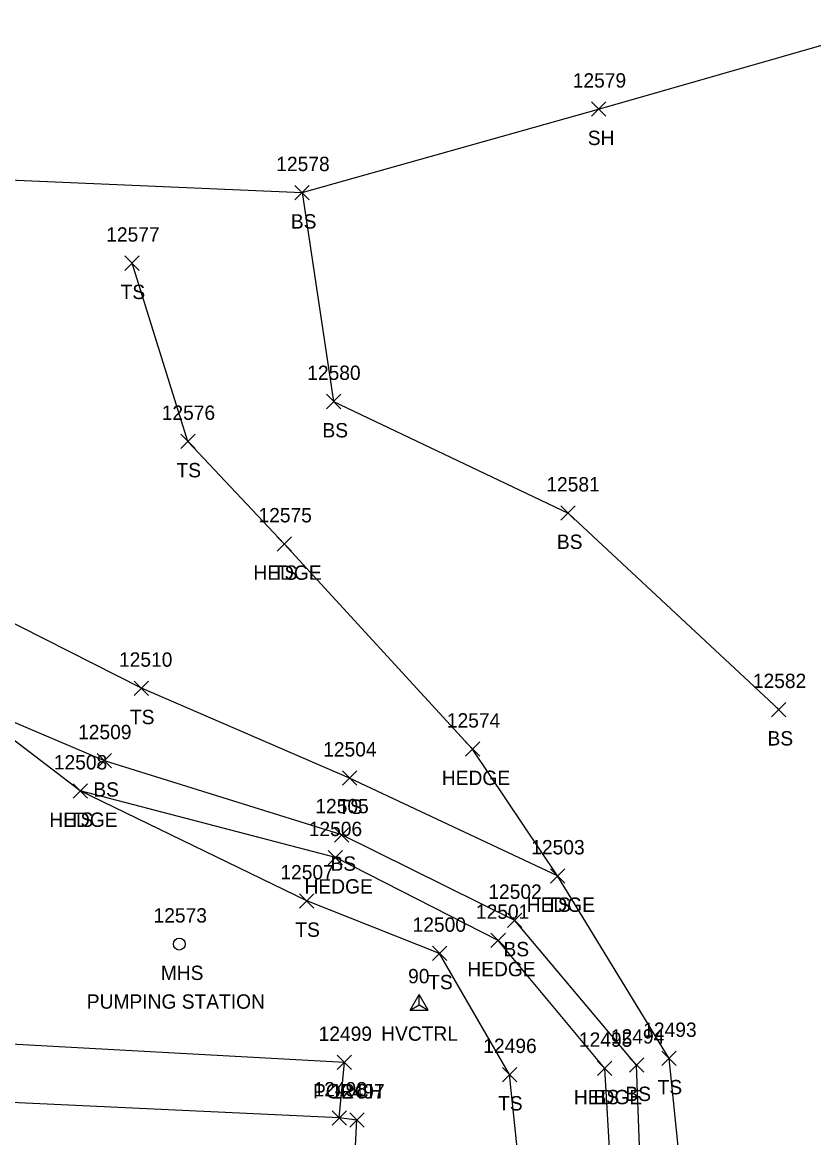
# Model space of a CAD drawing. Extents: x 1482574 to 1485769, y 580696 to 595649.
# Drawn here: x 1482847.5 to 1482957.7, y 584017.2 to 584172.5 of the extents above; entities that cross this region are included whole.
import ezdxf

# ---------------------------------------------------------------- set-up
doc = ezdxf.new("R2010")
doc.units = 0
for name, color, linetype in [('C_A', 7, 'Continuous'), ('C_I', 7, 'Continuous'), ('CPSM', 7, 'Continuous'), ('L_A', 7, 'Continuous'), ('L_I', 7, 'Continuous'), ('L_TIC', 7, 'Continuous'), ('LAHR', 7, 'Continuous'), ('LBC', 7, 'Continuous'), ('LBF', 7, 'Continuous'), ('LELB', 7, 'Continuous'), ('LSOGP', 7, 'Continuous'), ('U_A', 7, 'Continuous'), ('U_C', 7, 'Continuous'), ('U_I', 7, 'Continuous'), ('USMH', 7, 'Continuous')]:
    doc.layers.add(name, color=color, linetype=linetype)

msp = doc.modelspace()

# ---------------------------------------------------------------- linework, layer by layer
at = {"layer": 'CPSM'}
for p, q in [((1482901.5, 584035.01), (1482902.75, 584037.18)), ((1482904, 584035.01), (1482902.75, 584037.18)), ((1482902.75, 584035.73), (1482902.75, 584037.18)), ((1482901.5, 584035.01), (1482902.75, 584035.73)), ((1482902.75, 584035.73), (1482902.75, 584035.73)), ((1482902.75, 584035.73), (1482904, 584035.01)), ((1482901.5, 584035.01), (1482904, 584035.01))]:
    msp.add_line(p, q, dxfattribs=at)
at = {"layer": 'L_TIC'}
for points in [[(1482926.74, 584159.45), (1482928.74, 584161.45)], [(1482928.74, 584159.45), (1482926.74, 584161.45)], [(1482885.43, 584147.82), (1482887.43, 584149.82)], [(1482887.43, 584147.82), (1482885.43, 584149.82)], [(1482861.74, 584138), (1482863.74, 584140)], [(1482863.74, 584138), (1482861.74, 584140)], [(1482889.83, 584118.74), (1482891.83, 584120.74)], [(1482891.83, 584118.74), (1482889.83, 584120.74)], [(1482869.53, 584113.18), (1482871.53, 584115.18)], [(1482871.53, 584113.18), (1482869.53, 584115.18)], [(1482922.49, 584103.21), (1482924.49, 584105.21)], [(1482924.49, 584103.21), (1482922.49, 584105.21)], [(1482882.95, 584098.91), (1482884.95, 584100.91)], [(1482884.95, 584098.91), (1482882.95, 584100.91)], [(1482882.95, 584098.91), (1482884.95, 584100.91)], [(1482884.95, 584098.91), (1482882.95, 584100.91)], [(1482863.04, 584078.81), (1482865.04, 584080.81)], [(1482865.04, 584078.81), (1482863.04, 584080.81)], [(1482951.83, 584075.84), (1482953.83, 584077.84)], [(1482953.83, 584075.84), (1482951.83, 584077.84)], [(1482909.19, 584070.34), (1482911.19, 584072.34)], [(1482911.19, 584070.34), (1482909.19, 584072.34)], [(1482857.9, 584068.72), (1482859.9, 584070.72)], [(1482859.9, 584068.72), (1482857.9, 584070.72)], [(1482892.04, 584066.31), (1482894.04, 584068.31)], [(1482894.04, 584066.31), (1482892.04, 584068.31)], [(1482854.52, 584064.51), (1482856.52, 584066.51)], [(1482856.52, 584064.51), (1482854.52, 584066.51)], [(1482854.52, 584064.51), (1482856.52, 584066.51)], [(1482856.52, 584064.51), (1482854.52, 584066.51)], [(1482890.95, 584058.4), (1482892.95, 584060.4)], [(1482892.95, 584058.4), (1482890.95, 584060.4)], [(1482890.08, 584055.23), (1482892.08, 584057.23)], [(1482892.08, 584055.23), (1482890.08, 584057.23)], [(1482921.03, 584052.68), (1482923.03, 584054.68)], [(1482923.03, 584052.68), (1482921.03, 584054.68)], [(1482921.03, 584052.68), (1482923.03, 584054.68)], [(1482923.03, 584052.68), (1482921.03, 584054.68)], [(1482886.08, 584049.2), (1482888.08, 584051.2)], [(1482888.08, 584049.2), (1482886.08, 584051.2)], [(1482915.05, 584046.49), (1482917.05, 584048.49)], [(1482917.05, 584046.49), (1482915.05, 584048.49)], [(1482912.75, 584043.71), (1482914.75, 584045.71)], [(1482914.75, 584043.71), (1482912.75, 584045.71)], [(1482904.59, 584041.9), (1482906.59, 584043.9)], [(1482906.59, 584041.9), (1482904.59, 584043.9)], [(1482936.55, 584027.27), (1482938.55, 584029.27)], [(1482938.55, 584027.27), (1482936.55, 584029.27)], [(1482891.34, 584026.71), (1482893.34, 584028.71)], [(1482893.34, 584026.71), (1482891.34, 584028.71)], [(1482927.6, 584025.89), (1482929.6, 584027.89)], [(1482929.6, 584025.89), (1482927.6, 584027.89)], [(1482927.6, 584025.89), (1482929.6, 584027.89)], [(1482929.6, 584025.89), (1482927.6, 584027.89)], [(1482932.04, 584026.34), (1482934.04, 584028.34)], [(1482934.04, 584026.34), (1482932.04, 584028.34)], [(1482914.33, 584025.02), (1482916.33, 584027.02)], [(1482916.33, 584025.02), (1482914.33, 584027.02)], [(1482890.62, 584018.98), (1482892.62, 584020.98)], [(1482892.62, 584018.98), (1482890.62, 584020.98)], [(1482890.62, 584018.98), (1482892.62, 584020.98)], [(1482892.62, 584018.98), (1482890.62, 584020.98)], [(1482893.08, 584018.69), (1482895.08, 584020.69)], [(1482895.08, 584018.69), (1482893.08, 584020.69)]]:
    msp.add_lwpolyline(points, dxfattribs=at)
at = {"layer": 'LAHR'}
for points in [[(1482922.03, 584053.68), (1482910.19, 584071.34), (1482883.95, 584099.91)], [(1482928.6, 584026.89), (1482913.75, 584044.71), (1482891.08, 584056.23), (1482855.52, 584065.51), (1482838.91, 584078.18), (1482807.15, 584087.89)]]:
    msp.add_lwpolyline(points, dxfattribs=at)
at = {"layer": 'LBC'}
msp.add_lwpolyline([(1482837.55, 583990.35), (1482890.4, 583987.41), (1482892.38, 583987.48), (1482894.08, 584019.69), (1482891.62, 584019.98), (1482838.94, 584022.48)], dxfattribs=at)
at = {"layer": 'LBF'}
msp.add_lwpolyline([(1482891.62, 584019.98), (1482892.34, 584027.71), (1482839.85, 584030.58), (1482838.94, 584022.48)], dxfattribs=at)
at = {"layer": 'LELB'}
for points in [[(1482942.03, 583859.02), (1482934.27, 583897.38), (1482938.31, 583954.48), (1482940.22, 584002.41), (1482937.55, 584028.27), (1482922.03, 584053.68), (1482893.04, 584067.31), (1482864.04, 584079.81), (1482840.37, 584091.78), (1482809.38, 584097.57), (1482788.21, 584111.78), (1482800.36, 584152.56)], [(1482886.43, 584148.82), (1482890.83, 584119.74), (1482923.49, 584104.21), (1482952.83, 584076.84)], [(1482883.95, 584099.91), (1482870.53, 584114.18), (1482862.74, 584139)], [(1482935.97, 583858.21), (1482928.85, 583898.87), (1482930.75, 583906.84), (1482932.59, 583955.77), (1482933.96, 584002.2), (1482933.04, 584027.34), (1482916.05, 584047.49), (1482891.95, 584059.4), (1482858.9, 584069.72), (1482838.91, 584078.18)], [(1482919.81, 583833.79), (1482907.27, 583906.38), (1482912.01, 583925.67), (1482914.6, 583960.3), (1482917.87, 584001.6), (1482915.33, 584026.02), (1482905.59, 584042.9), (1482887.08, 584050.2), (1482855.52, 584065.51)], [(1482929.27, 583854.03), (1482919.13, 583901.83), (1482926.68, 583909.21), (1482929.31, 583956.52), (1482930.04, 584002.31), (1482928.6, 584026.89)]]:
    msp.add_lwpolyline(points, dxfattribs=at)
at = {"layer": 'LSOGP'}
msp.add_lwpolyline([(1482624.36, 583828.83), (1482673.16, 583862.27), (1482696.29, 583884.43), (1482694.49, 583917.75), (1482678.31, 583954.25), (1482684.74, 583977.37), (1482695.23, 584028.52), (1482699.57, 584054.68), (1482704.09, 584083.33), (1482704.84, 584111.05), (1482731.9, 584115.44), (1482800.36, 584152.56), (1482886.43, 584148.82), (1482927.74, 584160.45), (1482970.01, 584172.54)], dxfattribs=at)
at = {"layer": 'USMH'}
for p, q in [((1482869.33, 584044.19), (1482869.33, 584044.19)), ((1482870.16, 584044.19), (1482870.16, 584044.19))]:
    msp.add_line(p, q, dxfattribs=at)
msp.add_circle((1482869.33, 584044.19), 0.833, dxfattribs=at)

# ---------------------------------------------------------------- texts
at = {"layer": 'C_A'}
msp.add_text('HVCTRL', height=2, dxfattribs=at).set_placement((1482897.45, 584030.73))
at = {"layer": 'C_I'}
msp.add_text('90', height=2, dxfattribs=at).set_placement((1482901.2, 584038.73))
at = {"layer": 'L_A'}
for s, p in [('SH', (1482926.23, 584155.45)), ('BS', (1482884.87, 584143.82)), ('TS', (1482861.15, 584134)), ('BS', (1482889.27, 584114.74)), ('TS', (1482868.94, 584109.18)), ('BS', (1482921.93, 584099.21)), ('HEDGE', (1482879.65, 584094.91)), ('TS', (1482882.36, 584094.91)), ('TS', (1482862.45, 584074.81)), ('BS', (1482951.27, 584071.84)), ('HEDGE', (1482905.9, 584066.34)), ('BS', (1482857.35, 584064.72)), ('TS', (1482891.45, 584062.31)), ('HEDGE', (1482851.22, 584060.51)), ('TS', (1482853.93, 584060.51)), ('BS', (1482890.39, 584054.4)), ('HEDGE', (1482886.78, 584051.23)), ('HEDGE', (1482917.73, 584048.68)), ('TS', (1482920.44, 584048.68)), ('TS', (1482885.49, 584045.2)), ('BS', (1482914.49, 584042.49)), ('HEDGE', (1482909.45, 584039.71)), ('TS', (1482904, 584037.9)), ('PORCH', (1482887.96, 584022.71)), ('BS', (1482931.48, 584022.34)), ('TS', (1482935.96, 584023.27)), ('TS', (1482913.74, 584021.02)), ('HEDGE', (1482924.3, 584021.89)), ('BS', (1482927.04, 584021.89))]:
    msp.add_text(s, height=2, dxfattribs=at).set_placement(p)
at = {"layer": 'L_I'}
for s, p in [('12579', (1482924.14, 584163.45)), ('12578', (1482882.84, 584151.82)), ('12577', (1482859.15, 584142)), ('12580', (1482887.15, 584122.74)), ('12576', (1482866.88, 584117.18)), ('12581', (1482920.46, 584107.21)), ('12575', (1482880.36, 584102.91)), ('12575', (1482880.36, 584102.91)), ('12510', (1482860.93, 584082.81)), ('12582', (1482949.23, 584079.84)), ('12574', (1482906.6, 584074.34)), ('12509', (1482855.23, 584072.72)), ('12504', (1482889.37, 584070.31)), ('12508', (1482851.85, 584068.51)), ('12508', (1482851.85, 584068.51)), ('12505', (1482888.28, 584062.4)), ('12506', (1482887.36, 584059.23)), ('12503', (1482918.36, 584056.68)), ('12503', (1482918.36, 584056.68)), ('12507', (1482883.41, 584053.2)), ('12502', (1482912.38, 584050.49)), ('12501', (1482910.65, 584047.71)), ('12500', (1482901.83, 584045.9)), ('12499', (1482888.74, 584030.71)), ('12494', (1482929.45, 584030.34)), ('12493', (1482933.96, 584031.27)), ('12496', (1482911.68, 584029.02)), ('12495', (1482925, 584029.89)), ('12495', (1482925, 584029.89)), ('12498', (1482888.03, 584022.98)), ('12498', (1482888.03, 584022.98)), ('12497', (1482890.49, 584022.69))]:
    msp.add_text(s, height=2, dxfattribs=at).set_placement(p)
at = {"layer": 'U_A'}
msp.add_text('MHS', height=2, dxfattribs=at).set_placement((1482866.75, 584039.19))
at = {"layer": 'U_C'}
msp.add_text('PUMPING STATION', height=2, dxfattribs=at).set_placement((1482856.44, 584035.19))
at = {"layer": 'U_I'}
msp.add_text('12573', height=2, dxfattribs=at).set_placement((1482865.74, 584047.19))

doc.saveas('drawing.dxf')
